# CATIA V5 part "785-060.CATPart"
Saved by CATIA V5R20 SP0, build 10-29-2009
Part number: 785-060
Revision: ANY
Definition: UNKNOWN
Nomenclature: 785-060
Source: Unknown
Bounding box of the stored display mesh (mm): x -30 to 30, y -20 to 9, z -132 to 18
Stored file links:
  C:\Users\Utente\Desktop\IO LAVORO\3D X SITO CF\X 3D SITO CF 27-09-2020\785\785-060.CATPart
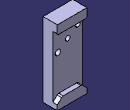
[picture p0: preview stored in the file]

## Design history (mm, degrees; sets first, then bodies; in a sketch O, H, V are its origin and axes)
Body1 "Smusso1" (main body)
  Solid1: solid without history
